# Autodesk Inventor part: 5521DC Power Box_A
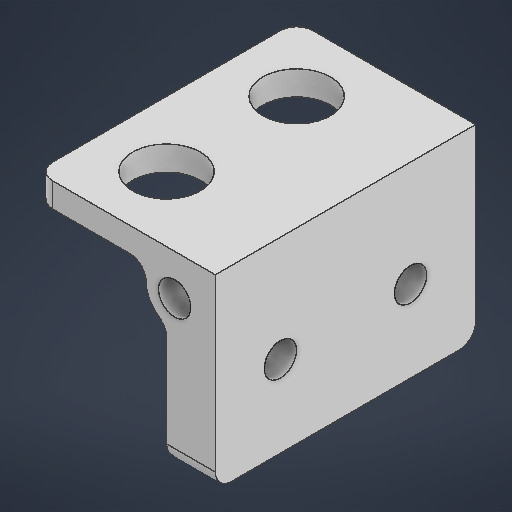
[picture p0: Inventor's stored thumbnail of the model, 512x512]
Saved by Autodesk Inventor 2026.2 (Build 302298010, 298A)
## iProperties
Created: 2026-05
Part Number: 5521DC Power Box_A
Material: 일반
Document SubType Name: Modeling
Designer: work
Density: 1 g/cm^3
Appearance: 기본값
Author: work
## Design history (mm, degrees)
sketch "스케치1"
  geometry: L1 (0, -16)-(0, 0); L2 (-8, 8)-(8, 8); L3 (8, 8)-(8, -24); L4 (8, -24)-(-8, -24); L5 (-8, -24)-(-8, 8); L6 (-8, 8)-(8, -24); L7 (8, 8)-(-8, -24); L8 (-8, 8)-(-14, 8); L9 (-14, 8)-(-14, -24); L10 (-14, -24)-(-8, -24); L11 (-8, -24)-(-8, 8); C1 r 4.15 at (0, 0); C2 r 4.15 at (0, -16); 2 further points
  constraints: 22 end point, 4 parallel, 3 midpoint, 2 centre point, 2 horizontal, 2 perpendicular, 1 coincident, 1 point on line, 1 vertical
  dimensions: "d0" = 8.3 diameter of C1; "d1" = 8.3 diameter of C2; "d2" = 16 distance of L1.start L1.end; "d3" = 8 distance from line of L3 L1.start; "d4" = 8 distance from line of L4 L1.start; "d5" = 6 distance of L9.end L10.end
extrude "돌출1" new body sketch "스케치1" distance "d6" = 3; taper "d7" = 0 deg
extrude "돌출2" join sketch "스케치1" distance "d8" = 3; taper "d10" = 0 deg; dims "d9" = 20, "d11" = 0
sketch "스케치2"
  geometry: L1 (32, 0)-(0, 0) reference; L2 (0, 0)-(0, -20) reference; L3 (32, -20)-(0, -20) reference; L4 (32, -20)-(32, 0) reference; L5 (16, 0)-(16, -20); L6 (0, -10)-(32, -10); 3 further points
  constraints: 4 end point, 4 midpoint, 1 point on line, 1 symmetric about line
  dimensions: "d13" = 16 distance of point (24, -10) point (8, -10)
hole "구멍1" sketch "스케치2" at (8, -10), (24, -10) diameter "d14" = 4; stored, may be unused: countersink angle "d18" = 90 deg, drill point angle "d20" = 118 deg; dims "d15" = 6, "d16" = 6.2, "d17" = 3, "d19" = 8
fillet "모깎기1" dims "d21" = 2
fillet "모깎기2" dims "d22" = 2
sketch "스케치3"
  geometry: L1 (-8, -18)-(-8, 3) reference; L2 (-8, 3)-(12, 3) reference; C1 r 2 at (-3, -2); C2 r 3.5 at (-3, -2); 1 further point
  constraints: 2 centre point, 1 coincident
  dimensions: "d23" = 4 diameter of C1; "d24" = 7 diameter of C2; "d25" = 5 distance from line of L1 C1.centre; "d26" = 5 distance from line of L2 C1.centre
extrude "돌출3" join sketch "스케치3" distance "d27" = 8; taper "d28" = 0 deg
extrude "돌출4" cut sketch "스케치3" distance "d29" = 8; taper "d30" = 0 deg
sketch "스케치4"
  geometry: L1 (2, -3.732)-(2, -5.354) reference; C1 r 3.5 at (3, -2); A1 r 2 centre (3, -2) between (1.5, -0.677) and (2, -3.732) reference; A2 r 2 centre (0, -2) between (1.5, -0.677) and (0.125, -0.004) reference; A3 r 3.5 centre (3, -2) between (0.125, -0.004) and (2, -5.354) reference; 3 further points
  constraints: 1 centre point, 1 coincident, 1 concentric
extrude "돌출5" join sketch "스케치4" distance "d31" = 2; taper "d32" = -60 deg
sketch "스케치5"
  geometry: L1 (0, 0)-(12, 0) reference; L2 (12, 3)-(12, 0) reference; L3 (-8, 3)-(12, 3) reference; L4 (-8, -18)-(-8, 3) reference; L5 (-2, -18)-(-8, -18) reference; L6 (-2, -5.354)-(-2, -18) reference; L7 (0, 0)-(12, 0) reference; L8 (-2, -5.354)-(-2, -18) reference; L9 (-0.125, -0.004)-(-2, -5.354); C1 r 2 at (-3, -2) reference; A1 r 3.5 centre (-3, -2) between (-2, -5.354) and (-0.125, -0.004) reference; A2 r 2 centre (0, -2) between (0, 0) and (-0.125, -0.004) reference; A3 r 2 centre (2.5, -2) between (2.5, 0) and (0.5, -2); A4 r 2 centre (0, -6.61) between (-1.091, -4.933) and (-2, -6.61); A5 r 3.5 centre (-3, -2) between (-2, -5.354) and (-0.125, -0.004) reference; A6 r 1.323 centre (1.188, -0.172) between (2.5, 0) and (-0.125, -0.004); A7 r 0.685 centre (-2.273, -5.982) between (-2, -5.354) and (-2, -6.61); 1 further point
  constraints: 10 point on circle, 5 tangent, 4 centre point, 2 end point, 2 point on line
  dimensions: "d33" = 2 radius of A4; "d34" = 2 radius of A3
extrude "돌출6" join sketch "스케치5" distance "d35" = 8; taper "d36" = 0 deg
sketch "스케치6"
  geometry: L1 (0, 2.23)-(0, 8) reference; L2 (0.65, 0)-(2.5, 0) reference; L3 (2.5, -24)-(2.5, 0) reference; L4 (-9.5, -24)-(2.5, -24) reference; L5 (-11.5, 6)-(-11.5, -22) reference; L6 (0, 8)-(-9.5, 8) reference; L7 (2, 8)-(2, 0) reference; C1 r 4.15 at (-3.5, -16) reference; C2 r 5.5 at (-3.5, 0); A1 r 4.15 centre (-3.5, 0) between (0, 2.23) and (0.65, 0) reference; A2 r 2 centre (-9.5, -22) between (-11.5, -22) and (-9.5, -24) reference; A3 r 2 centre (-9.5, 6) between (-9.5, 8) and (-11.5, 6) reference; 1 further point
  constraints: 1 centre point, 1 coincident, 1 tangent
extrude "돌출7" cut sketch "스케치6" extent not by distance; stored distance "d37" = 0; taper "d38" = 0 deg
node "작업 평면1"
node "솔리드1"
mirror "미러1"
node "투영된 루프1"
node "투영된 루프2"
node "투영된 루프3"
node "투영된 루프4"
feature "A9D066F2-1C7D-4E18-AEED-F7BC21143FA4" dims "d14" = 4, "d15" = 6, "d16" = 6.2, "d17" = 3, "d18" = 90 deg, "d19" = 8, "d20" = 118 deg
